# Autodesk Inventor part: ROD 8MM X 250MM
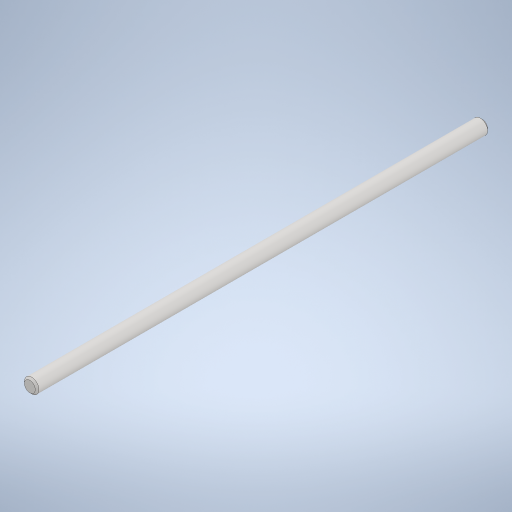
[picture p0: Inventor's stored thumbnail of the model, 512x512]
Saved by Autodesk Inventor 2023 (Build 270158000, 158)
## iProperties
Created: 2025-07
Part Number: ROD 8MM X 250MM
Material: Generic
Document SubType Name: Modeling
Designer: erjon
Density: 1 g/cm^3
Appearance: Default
Author: erjon
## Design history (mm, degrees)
feature "Base1"
body "Solid1"
